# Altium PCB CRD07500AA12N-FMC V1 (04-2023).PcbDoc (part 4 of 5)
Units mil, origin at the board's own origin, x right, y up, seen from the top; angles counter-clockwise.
Board outline 8000 x 8000 mil, 4 copper layers (Top Layer, Layer 1, Layer 2, Bottom Layer), stack 107.988 mil thick; 393 components, 213 nets, 1142 pads, 380 vias.
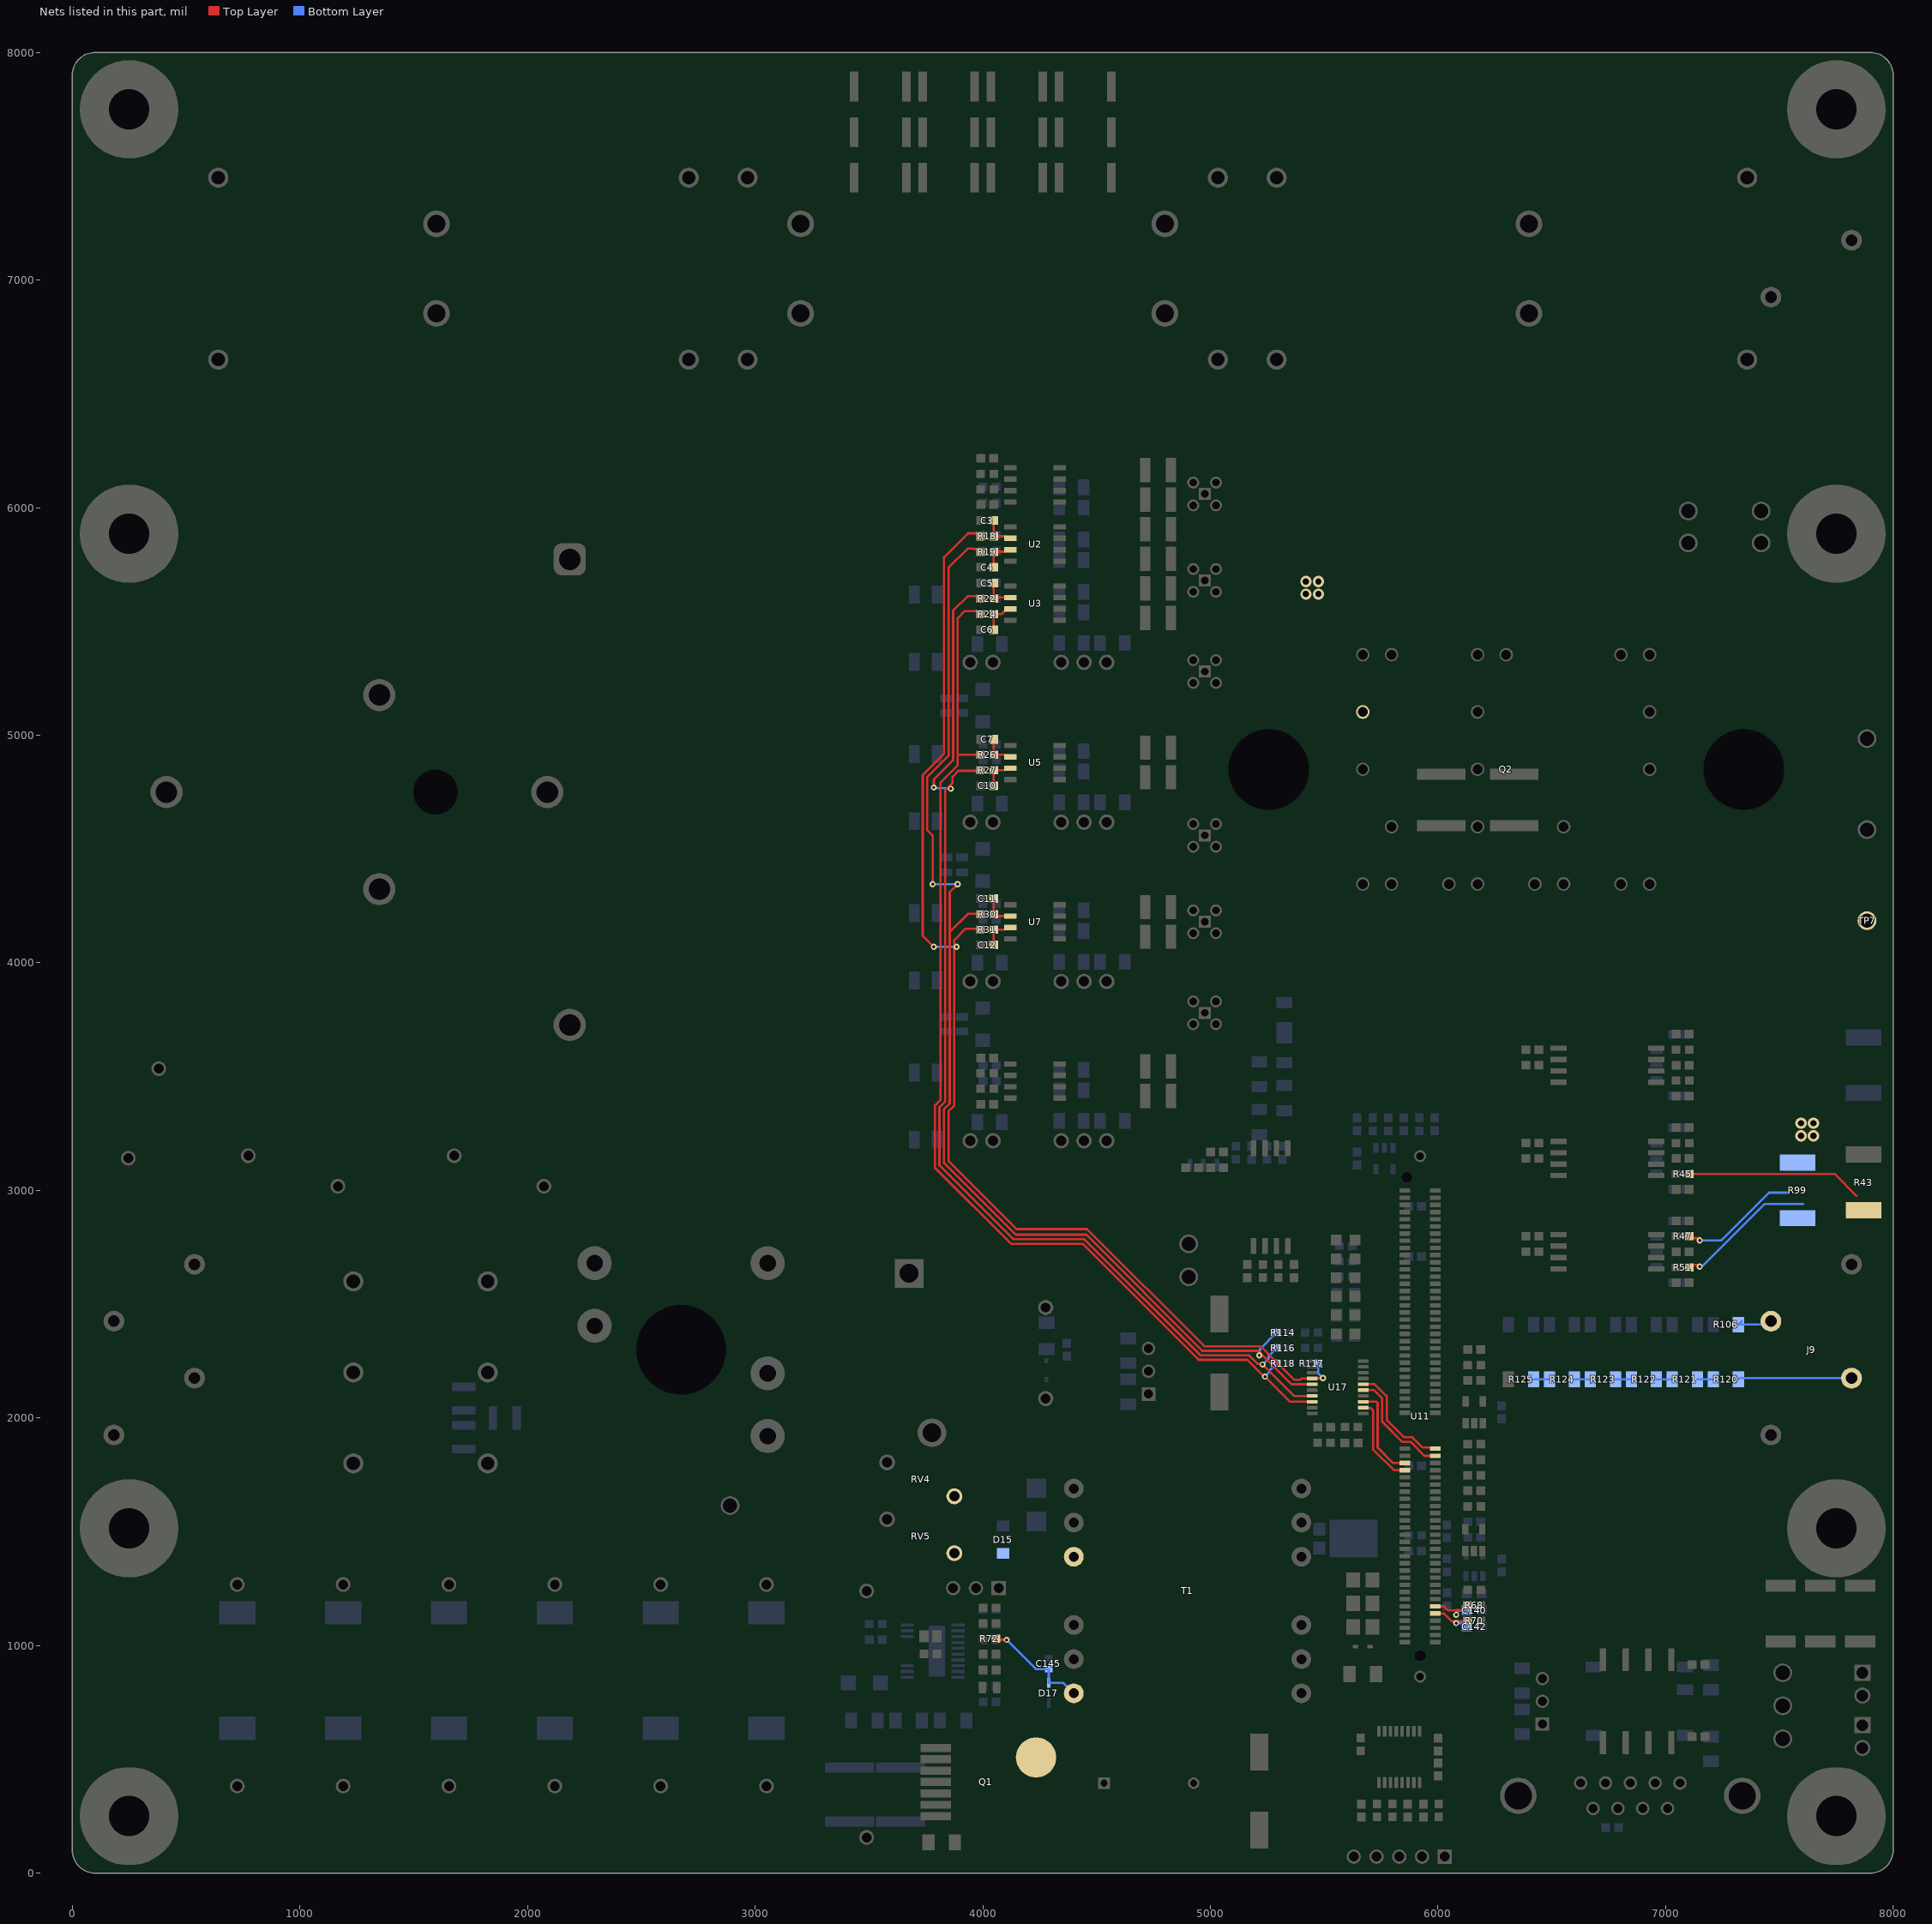
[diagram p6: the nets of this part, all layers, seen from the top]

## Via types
v1: diameter 27, hole 13, Top Layer to Bottom Layer, tented both sides, 367 vias
v2: diameter 50, hole 28, Top Layer to Bottom Layer, tented both sides, 13 vias

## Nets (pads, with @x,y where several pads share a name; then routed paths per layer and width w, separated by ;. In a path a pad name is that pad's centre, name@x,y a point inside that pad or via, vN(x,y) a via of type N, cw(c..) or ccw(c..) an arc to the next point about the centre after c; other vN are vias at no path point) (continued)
V_HS: R19.1 R30.1 R114.2 U17.15 | length 5303.9
  Top Layer w10: v1(3780,4345) 3780,4558.95 3756.5,4582.45 3756.5,4816.65 3850,4910.15 3850,5736.51 3933.19,5819.7 3956.81,5819.7 3957.55,5818.96 3978.42,5818.96 R19.1@3991.38,5806 ; v1(3890,4345) 3855,4310 3855,4135 ; R30.1@3991.38,4214 3990.38,4215 3935,4215 3855,4135 ; U17.15@5447.8,2147.8 5357.2,2147.8 5210,2295 4965.15,2295 4455.15,2805 4145,2805 3830,3120 3830,3356.35 3855,3381.35 3855,4135
  Bottom Layer w10: v1(3780,4345) v1(3890,4345) ; v1(5215,2275) 5218.25,2278.25 5218.25,2302.78 5290.47,2375 R114.2@5291.38,2375
V_HS+_FILT: C11.1 R30.2 U7.2 | length 141.7
  Top Layer w10: R30.2@4048.62,4214 4057.62,4205 U7.2@4121.73,4205 ; R30.2@4048.62,4217.2 4048.58,4217.25 C11.1@4048.58,4282
V_HS-_FILT: C4.1 R19.2 U2.3 | length 144.9
  Top Layer w10: C4.1@4048.58,5738 R19.2@4048.62,5806 R19.2@4048.62,5806 4096.98,5806 4105.98,5815 U2.3@4121.73,5815
V_HS_PWM: U11.53 U17.5 | length 476.7
  Top Layer w10: U17.5@5692.72,2122.87 5718.68,2122.87 5755,2086.56 5755,1982.99 5842.99,1895 5879.72,1895 5941.17,1833.54 U11.53@5988.86,1833.54
V_LS: R18.1 R31.1 R117.2 U17.14 | length 5321.1
  Top Layer w10: v1(3785,4070) 3736.5,4118.5 3736.5,4824.93 3830,4918.43 3830,5781.51 3935.6,5887.11 3956.48,5887.11 3956.64,5886.96 3978.42,5886.96 R18.1@3991.38,5874 ; R31.1@3991.38,4146 3987.38,4150 3925,4150 3875,4100 3875,4070 3875,3373.07 3850,3348.07 3850,3128.43 4148.43,2830 4458.43,2830 4973.43,2315 5220,2315 5367,2168 5395.39,2168 5400.78,2173.39 U17.14@5447.8,2173.39 5448.6,2174.19 5494.19,2174.19 v1(5495,2175)
  Bottom Layer w10: v1(3785,4070) v1(3885,4070) ; R117.2@5473.62,2240 5473.62,2196.38 v1(5495,2175)
V_LS+_FILT: C3.1 R18.2 U2.2 | length 145.9
  Top Layer w10: C3.1@4048.58,5943 R18.2@4048.62,5874 R18.2@4048.62,5874 4096.98,5874 4105.98,5865 U2.2@4121.73,5865
V_LS-_FILT: C12.1 R31.2 U7.3 | length 144.9
  Top Layer w10: C12.1@4048.58,4078 R31.2@4048.62,4146 R31.2@4048.62,4146 4096.98,4146 4105.98,4155 U7.3@4121.73,4155
V_LS_PWM: U11.55 U17.6 | length 474.2
  Top Layer w10: U17.6@5692.72,2148.46 5721.38,2148.46 5775,2094.84 5775,1991.27 5851.27,1915 5888,1915 5933.12,1869.88 5984.02,1869.88 U11.55@5988.86,1865.04
V_MEAS: C140.1 R68.2 U11.11 | length 237.4
  Top Layer w10: U11.11@5988.86,1172.13 6027.53,1172.13 6045.99,1153.67 6079.77,1153.67 6080,1153.43 ; v1(6080,1135) 6080,1153.43 ; R68.2@6131.38,1177 6130.47,1177 6108.61,1155.14 6081.7,1155.14 6080,1153.43
  Bottom Layer w10: v1(6080,1135) 6083.25,1138.25 6083.25,1143.65 6092.92,1153.32 6125.78,1153.32 C140.1@6127.45,1155
V_OUT: J9.3 R43.2 R45.1 R106.1 | length 946.6
  Top Layer w10: R45.1@7103.62,3072 7743.35,3072 7840,2975.35
  Bottom Layer w10: R106.1@7335.12,2425 R106.1@7320.12,2410 7447.83,2410 J9.3@7462.83,2425
VAR: RV4.2 RV5.1
W: Q2.W R47.1 R99.1 TP7.1 | length 533.2
  Top Layer w10: R47.1@7103.62,2808 7103.62,2803.86 7117.48,2790 v1@7150,2790
  Bottom Layer w10: v1(7150,2780) 7245,2780 7455,2990 7540,2990
  other v2: 7595,3240 7650,3240 7595,3295 7650,3295 5420,5620 5475,5620 5420,5675 5475,5675
W0: R120.2 R121.1 | length 69.6
  Bottom Layer w10: R121.1@7140.24,2170 R120.2@7209.88,2170
W1: R121.2 R122.1 | length 69.9
  Bottom Layer w10: R122.1@6960.12,2170 R121.2@7030,2170
W2: R122.2 R123.1 | length 69.8
  Bottom Layer w10: R123.1@6780.12,2170 R122.2@6849.88,2170
W3: R123.2 R124.1 | length 69.6
  Bottom Layer w10: R124.1@6600.24,2170 R123.2@6669.88,2170
W4: R124.2 R125.1 | length 69.8
  Bottom Layer w10: R125.1@6420.24,2170 R124.2@6490,2170
W_HS: R24.1 R26.1 R118.2 U17.18 | length 4842.2
  Top Layer w10: R26.1@3991.38,4914 3890,4914 ; R24.1@3991.38,5532 3978.42,5544.96 3957.55,5544.96 3956.81,5545.7 3920.7,5545.7 3890,5515 3890,4914 ; U17.18@5447.8,2071.02 5350.2,2071.02 v1(5240,2181.23) 5235.49,2181.23 5161.72,2255 4948.58,2255 4438.58,2765 4125,2765 3790,3100 3790,3372.92 3815,3397.92 3815,4793.28 3890,4868.28 3890,4914
  Bottom Layer w10: v1(5240,2181.23) 5240,2182.46 5259.54,2201.99 5259.54,2209.07 5290.47,2240 R118.2@5291.38,2240
W_HS+_FILT: C7.1 R26.2 U5.2 | length 144.9
  Top Layer w10: C7.1@4048.58,4982 R26.2@4048.62,4914 R26.2@4048.62,4914 4096.98,4914 4105.98,4905 U5.2@4121.73,4905
W_HS-_FILT: C6.1 R24.2 U3.3 | length 150.7
  Top Layer w10: C6.1@4048.58,5464 R24.2@4048.62,5532 R24.2@4048.62,5532 4082.98,5532 4105.98,5555 U3.3@4121.73,5555
W_HS_PWM: U11.50 U17.2 | length 392.3
  Top Layer w10: U17.2@5677.2,2045.43 5679.92,2042.72 5705.89,2042.72 5715,2033.6 5715,1861.72 5806.16,1770.55 U11.50@5855,1770.55
W_LS: R22.1 R27.1 R116.2 U17.17 | length 5083.2
  Top Layer w10: v1(3785,4770) 3785,4805 3870,4890 3870,5547.51 3933.19,5610.7 3980.67,5610.7 R22.1@3991.38,5600 ; v1(3860,4765) 3841.35,4765 ; R27.1@3991.38,4846 3988.88,4843.5 3893.5,4843.5 3867.43,4817.43 3867.43,4791.07 3841.35,4765 ; U17.17@5447.8,2096.61 5368.08,2096.61 5226.75,2237.95 5207.05,2237.95 5170,2275 4956.86,2275 4446.86,2785 4135,2785 3810,3110 3810,3364.64 3835,3389.64 3835,4758.65 3841.35,4765
  Bottom Layer w10: v1(3785,4770) 3787.5,4767.5 3857.5,4767.5 v1(3860,4765) ; v1(5230,2234.69) 5256.53,2261.23 5256.53,2273.06 5290.47,2307 R116.2@5291.38,2307
W_LS+_FILT: C5.1 R22.2 U3.2 | length 143.2
  Top Layer w10: C5.1@4048.58,5668 C5.1@4048.58,5668 R22.2@4048.62,5600 4053.62,5605 U3.2@4121.73,5605
W_LS-_FILT: C10.1 R27.2 U5.3 | length 144.9
  Top Layer w10: C10.1@4048.58,4778 R27.2@4048.62,4846 R27.2@4048.62,4846 4096.98,4846 4105.98,4855 U5.3@4121.73,4855
W_LS_PWM: U11.52 U17.3 | length 388.7
  Top Layer w10: U17.3@5692.72,2071.69 5729.14,2071.69 5735,2065.84 5735,1870 5802.95,1802.05 U11.52@5855,1802.05
W_MEAS: C142.1 R70.2 U11.9 | length 219.9
  Top Layer w10: U11.9@5988.86,1140.63 6027.48,1140.63 6061.61,1106.5 v1@6080,1106.5 ; v1(6080,1098) v1@6080,1106.5 ; R70.2@6131.38,1109 6128.88,1106.5 v1@6080,1106.5
  Bottom Layer w10: v1(6080,1098) 6080.08,1097.92 6109.64,1097.92 6124.57,1083 C142.1@6127.45,1083
W_OUT: J9.2 R51.1 R99.2 R120.1 | length 1117.5
  Top Layer w10: R51.1@7103.62,2672 7138.4,2672 7145.4,2665 v1(7150,2665)
  Bottom Layer w10: v1(7150,2665) 7153.25,2668.25 7163.25,2668.25 7435.35,2940.35 7605,2940.35 ; R120.1@7320.12,2170 7325.12,2175 J9.2@7817.17,2175
XFMR3: D15.2 Q1.8 T1.3 | length 26.1
  Top Layer w10: Q1.8@4235.66,507.76 Q1.8@4240,512.1 ; T1.3@4380,1390 T1.3@4400,1390
XFMR6: C145.1 D17.2 R72.2 T1.6 | length 476.6
  Top Layer w10: R72.2@4058.62,1030 4063.62,1025 v1(4105,1025)
  Bottom Layer w10: v1(4105,1025) 4233.62,896.38 C145.1@4290,896.38 D17.2@4290,835.28 4354.72,835.28 T1.6@4400,790
pads on no net: D1.6 HS1.3 HS1.4 J13.1 J13.4 J13.6 J13.8 L1.MH1 MH1.1 MH2.1 MH3.1 MH4.1 Q2.MH1 Q2.MH2 T1.2 T1.4 T1.7 T1.12 U11. U11.1 U11.2 U11.3 U11.4 U11.5 U11.6 U11.7 U11.8 U11.12 U11.14 U11.15 U11.18 U11.20 U11.21 U11.23 U11.24 U11.25 U11.26 U11.27 U11.28 U11.31 U11.32 U11.33 U11.34 U11.36 U11.37 U11.39 U11.40 U11.41 U11.42 U11.43 U11.44 U11.45 U11.54 U11.56 U11.57 U11.58 U11.59 U11.60 U11.61 U11.62 U11.63 U11.64 U11.66 U11.67 U11.69 U11.71 U11.72 U11.73 U11.75 U11.76 U11.77 U11.78 U11.79 U11.80 U11.81 U11.82 U11.85 U11.86 U11.89 U11.90 U11.91 U11.92 U11.94 U11.104 U11.106 U11.110 U11.113 U11.114 U11.115 U11.116 U11.117 U11.118 U11.119 U11.121 U11.122 U17.13 U17.16 U22.5 U22.6 U22.7 U22.10 U22.11 U22.12 U31.8

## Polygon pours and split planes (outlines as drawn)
V on Top Layer "V_L01_P141" (solid, pour order 141): 26 vertices, not listed, extent 6115,3070 7970,5155
G2 on Top Layer "G2_L01_P238" (solid, pour order 238): 6845,5450 6900,5395 6900,5387.5 6900,5325 6960,5325 6960,5495 5255,5495 5150,5600 5150,5805 5150,6220 4800,6220 4800,5980 5075,5980 5075,5570 5195,5450
G4 on Top Layer "G4_L01_P221" (solid, pour order 221): 6090,5395 6090,5390 6145,5335 6145,5325 6205,5325 6205,5440 5180,5440 5025,5595 5025,5960 4800,5960 4800,5720 4955,5720 4955,5585 5145,5395
G6 on Top Layer "G6_L01_P123" (solid, pour order 123): 4895,5460.84 4950,5405.84 4950,5395 4950,5255 5000,5255 5000,5420 5095,5325 5705,5325 5705,5385 5130,5385 4915,5600 4915,5700 4800,5700 4800,5460.84
C_FILT on Top Layer "C_FILT_L01_P047" (solid, pour order 47): 21 vertices, not listed, extent 930,2325 2385,5265
U on Top Layer "U_L01_P358" (solid, pour order 358): 7120,5020 7225,5125 7610,5125 7945,5125 7945,5315 7155,5315 7030,5190 6845,5190 6845,5020
G1 on Top Layer "G1_L01_P078" (solid, pour order 78): 18 vertices, not listed, extent 4800,3360 6960,4380
G3 on Top Layer "G3_L01_P054" (solid, pour order 54): 4920,4105 4950,4075 6260,4075 6390,4205 6390,4380 6594.94,4380 6594.95,4329.95 6290,4025 4800,4025 4800,4300 4920,4300 4920,4200 5025,4200 5025,4160 4920,4160
G5 on Top Layer "G5_L01_P053" (solid, pour order 53): 23 vertices, not listed, extent 4800,4170 6220,5000
G5H on Top Layer "G5H_L01_P192" (solid, pour order 192): 4310,4840 4310,4870 4740,4870 4740,4760 4425,4760 4425,4840
G5L on Top Layer "G5L_L01_P191" (solid, pour order 191): 4310,4920 4310,4890 4740,4890 4740,5000 4425,5000 4425,4920
G3H on Top Layer "G3H_L01_P188" (solid, pour order 188): 4310,4140 4310,4170 4740,4170 4740,4060 4425,4060 4425,4140
G3L on Top Layer "G3L_L01_P183" (solid, pour order 183): 4310,4220 4310,4190 4740,4190 4740,4300 4425,4300 4425,4220
G1H on Top Layer "G1H_L01_P180" (solid, pour order 180): 4310,3440 4310,3470 4720,3470 4720,3360 4425,3360 4425,3440
G1L on Top Layer "G1L_L01_P177" (solid, pour order 177): 4310,3520 4310,3490 4720,3490 4720,3600 4425,3600 4425,3520
G2L on Top Layer "G2L_L01_P203" (solid, pour order 203): 4310,6140 4310,6110 4740,6110 4740,6220 4425,6220 4425,6140
B_FILT on Top Layer "B_FILT_L01_P046" (solid, pour order 46): 1265,4425 1265,4215 1970,4215 2375,3810 2375,2960 2965,2370 2965,2120 3170,2120 3170,2300 2505,2965 2505,3940 2020,4425
A_FILT on Top Layer "A_FILT_L01_P045" (solid, pour order 45): 2805,3190 3245,2750 3245,2600 3030,2600 2655,2975 2655,4030 1995,4690 1995,4850 2155,4850 2805,4200
+3.3V on Top Layer "+3.3V_L01_P014" (solid, pour order 14): 33 vertices, not listed, extent 5625,460 7945,1070
SL on Top Layer "SL_L01_P246" (solid, pour order 246): 4925,3270 4925,3180 4925,3080 5020,3080 5020,3200 5090,3200 5090,3115 5370,3115 5370,3135 5265,3135 5265,3270
XFMR3 on Top Layer "XFMR3_L01_P295" (solid, pour order 295): 4170,645 4140,615 4115,615 4115,170 4405,170 4405,645 4340,645 4340,1280 4390,1330 4460,1330 4460,1445 4170,1445
GND on Top Layer "GND_L01_P314" (solid, pour order 314): 5165,105 5300,105 5300,335 5165,335
DC+ on Top Layer "DC+_L01_P348" (solid, pour order 348): 4585,7535 4635,7585 4925,7585 4925,7535 4975,7535 4975,7395 5080,7395 5080,7920 4545,7920 4545,7385 4585,7385
BLEED1 on Top Layer "BLEED1_L01_P346" (solid, pour order 346): 4245,7920 4355,7920 4355,7385 4245,7385
EGND1 on Top Layer "EGND1_L01_P342" (solid, pour order 342): 7435,1295 7435,1205 7925,1205 7925,1295
GND on Top Layer "GND_L01_P319" (solid, pour order 319): 5745,1360 5745,835 5670,835 5670,1360
+12V on Top Layer "+12V_L01_P318" (solid, pour order 318): 5560,1360 5560,835 5650,835 5650,1360
B on Top Layer "B_L01_P019" (solid, pour order 19): 100,2515 100,2355 875,2355 1110,2120 1315,2120 1315,2280 1170,2280 935,2515
C on Top Layer "C_L01_P394" (solid, pour order 394): 455,2255 455,2095 615,2095 990,1720 1315,1720 1315,1880 1060,1880 685,2255
DC+ on Top Layer "DC+_L01_P391" (solid, pour order 391): 5905,4568.03 5905,4635 6445,4635 6445,4568.03
DC- on Top Layer "DC-_L01_P390" (solid, pour order 390): 5905,4880 5905,4800 6445,4800 6445,4880
N_X_O on Top Layer "N_X_O_L01_P388" (solid, pour order 388): 2065,435 2065,330 3105,330 3105,435
-3V_LS on Top Layer "-3V_LS_L01_P197" (solid, pour order 197): 4310,5925 4380,5925 4380,5960 4405,5960 4405,5900 4310,5900
+3.3V on Top Layer "+3.3V_L01_P370" (solid, pour order 370): 6465,2670 6465,2605 6570,2605 6570,2670
GND on Top Layer "GND_L01_P369" (solid, pour order 369): 6475,2845 6475,2790 6570,2790 6570,2845
+3.3V on Top Layer "+3.3V_L01_P368" (solid, pour order 368): 6465,3080 6465,3015 6570,3015 6570,3080
GND on Top Layer "GND_L01_P367" (solid, pour order 367): 6475,3255 6475,3200 6570,3200 6570,3255
V_OUT on Top Layer "V_OUT_L01_P362" (solid, pour order 362): 7650,2375 7650,2710 7760,2820 7970,2820 7970,3000 7650,3000 7395,2745 7395,2375
S5 on Top Layer "S5_L01_P155" (solid, pour order 155): 6920,2790 6920,2885 7070,2885 7070,2845 7000,2845 7000,2790
+5V_V_HS on Top Layer "+5V_V_HS_L01_P142" (solid, pour order 142): 6920,3080 6920,2985 7070,2985 7070,3025 7000,3025 7000,3080
S3 on Top Layer "S3_L01_P151" (solid, pour order 151): 6920,3200 6920,3295 7070,3295 7070,3255 7000,3255 7000,3200
+5V_W_HS on Top Layer "+5V_W_HS_L01_P154" (solid, pour order 154): 6920,2670 6920,2575 7070,2575 7070,2615 7000,2615 7000,2670
S3 on Top Layer "S3_L01_P156" (solid, pour order 156): 7080,3025 7080,2985 7160,2985 7160,3050 7135,3050 7135,3025
S5 on Top Layer "S5_L01_P173" (solid, pour order 173): 7080,2615 7080,2575 7160,2575 7160,2640 7135,2640 7135,2615
-3V_U_HS on Top Layer "-3V_U_HS_L01_P174" (solid, pour order 174): 4310,3600 4310,3540 4370,3540 4370,3600
+15V_U_HS on Top Layer "+15V_U_HS_L01_P175" (solid, pour order 175): 4310,3360 4310,3420 4370,3420 4370,3360
-3V_V_HS on Top Layer "-3V_V_HS_L01_P181" (solid, pour order 181): 4310,4300 4310,4240 4370,4240 4370,4300
+15V_V_HS on Top Layer "+15V_V_HS_L01_P182" (solid, pour order 182): 4310,4060 4310,4120 4370,4120 4370,4060
-3V_W_HS on Top Layer "-3V_W_HS_L01_P189" (solid, pour order 189): 4310,5000 4310,4940 4370,4940 4370,5000
+15V_W_HS on Top Layer "+15V_W_HS_L01_P190" (solid, pour order 190): 4310,4760 4310,4820 4370,4820 4370,4760
-3V_LS on Top Layer "-3V_LS_L01_P193" (solid, pour order 193): 4310,5700 4310,5640 4370,5640 4370,5700
+15V_LS on Top Layer "+15V_LS_L01_P194" (solid, pour order 194): 4310,5460 4310,5520 4370,5520 4370,5460
G6L on Top Layer "G6L_L01_P195" (solid, pour order 195): 4310,5620 4310,5590 4740,5590 4740,5700 4425,5700 4425,5620
G6H on Top Layer "G6H_L01_P196" (solid, pour order 196): 4310,5540 4310,5570 4740,5570 4740,5460 4425,5460 4425,5540
+15V_LS on Top Layer "+15V_LS_L01_P198" (solid, pour order 198): 4310,5710 4310,5780 4370,5780 4370,5710
G4L on Top Layer "G4L_L01_P199" (solid, pour order 199): 4310,5880 4310,5850 4740,5850 4740,5960 4425,5960 4425,5880
G4H on Top Layer "G4H_L01_P200" (solid, pour order 200): 4310,5800 4310,5830 4740,5830 4740,5720 4425,5720 4425,5800
-3V_LS on Top Layer "-3V_LS_L01_P201" (solid, pour order 201): 4310,6190 4310,6160 4405,6160 4405,6190
+15V_LS on Top Layer "+15V_LS_L01_P202" (solid, pour order 202): 4310,5940 4310,6040 4365,6040 4365,5940
G2H on Top Layer "G2H_L01_P220" (solid, pour order 220): 4310,6060 4310,6090 4740,6090 4740,5980 4425,5980 4425,6060
+5V on Top Layer "+5V_L01_P247" (solid, pour order 247): 4090,3600 4090,3540 4155,3540 4155,3600
GND on Top Layer "GND_L01_P264" (solid, pour order 264): 4090,3360 4090,3420 4155,3420 4155,3360
+5V on Top Layer "+5V_L01_P265" (solid, pour order 265): 4090,4300 4090,4240 4155,4240 4155,4300
GND on Top Layer "GND_L01_P266" (solid, pour order 266): 4090,4060 4090,4120 4155,4120 4155,4060
+5V on Top Layer "+5V_L01_P267" (solid, pour order 267): 4090,5000 4090,4940 4155,4940 4155,5000
GND on Top Layer "GND_L01_P268" (solid, pour order 268): 4090,4760 4090,4820 4155,4820 4155,4760
+5V on Top Layer "+5V_L01_P269" (solid, pour order 269): 4090,5700 4090,5640 4155,5640 4155,5700
GND on Top Layer "GND_L01_P270" (solid, pour order 270): 4090,5460 4090,5520 4155,5520 4155,5460
+5V on Top Layer "+5V_L01_P271" (solid, pour order 271): 4090,5960 4090,5900 4155,5900 4155,5960
GND on Top Layer "GND_L01_P272" (solid, pour order 272): 4090,5720 4090,5780 4155,5780 4155,5720
+5V on Top Layer "+5V_L01_P273" (solid, pour order 273): 4090,6220 4090,6160 4155,6160 4155,6220
GND on Top Layer "GND_L01_P281" (solid, pour order 281): 4090,5980 4090,6040 4155,6040 4155,5980
DC- on Top Layer "DC-_L01_P349" (solid, pour order 349): 3080,7585 3025,7530 3025,7395 2920,7395 2920,7920 3455,7920 3455,7385 3415,7385 3415,7533.6 3363.6,7585
BLEED2 on Top Layer "BLEED2_L01_P345" (solid, pour order 345): 3645,7920 3755,7920 3755,7385 3645,7385
GND_ISO on Top Layer "GND_ISO_L01_P344" (solid, pour order 344): 7150,630 7150,570 7130,570 7130,540 7195,540 7195,630
GND on Top Layer "GND_L01_P332" (solid, pour order 332): 7390,1070 7390,975 7945,975 7945,1070
GND on Top Layer "GND_L01_P327" (solid, pour order 327): 6705,990 6705,885 6780,885 6780,990
GND on Top Layer "GND_L01_P323" (solid, pour order 323): 7145,995 7145,880 7215,880 7215,995
+5V_LS on Top Layer "+5V_LS_L01_P240" (solid, pour order 240): 5080,3080 5080,3190 5035,3190 5035,3080
+12V on Top Layer "+12V_L01_P322" (solid, pour order 322): 5000,2195 5000,2030 5125,2030 5125,2195
GND on Top Layer "GND_L01_P317" (solid, pour order 317): 5000,2535 5000,2375 5125,2375 5125,2535
GND_ISO on Top Layer "GND_ISO_L01_P316" (solid, pour order 316): 6710,630 6710,520 6780,520 6780,630
+5V_ISO on Top Layer "+5V_ISO_L01_P315" (solid, pour order 315): 7140,630 7140,575 7105,575 7105,515 7000,515 7000,630
+12V on Top Layer "+12V_L01_P313" (solid, pour order 313): 5165,615 5295,615 5295,410 5165,410
GND on Top Layer "GND_L01_P305" (solid, pour order 305): 6475,3665 6475,3610 6570,3610 6570,3665
+3.3V on Top Layer "+3.3V_L01_P312" (solid, pour order 312): 6465,3490 6465,3425 6570,3425 6570,3490
N_X_I on Top Layer "N_X_I_L01_P304" (solid, pour order 304): 1450,485 1500,435 1710,435 1710,330 670,330 670,435 1340,435 1390,485 1390,1490 1470,1570 1470,1995 1520,1995 1520,1540 1450,1470
FLY_S on Top Layer "FLY_S_L01_P289" (solid, pour order 289): 3705,80 3800,80 3800,225 3865,225 3865,470 3705,470
DC- on Top Layer "DC-_L01_P282" (solid, pour order 282): 3850,195 3850,75 4000,75 4000,195
+15V_LS on Top Layer "+15V_LS_L01_P239" (solid, pour order 239): 4870,3080 4915,3080 4915,3170 4870,3170
S1 on Top Layer "S1_L01_P157" (solid, pour order 157): 7080,3435 7080,3395 7160,3395 7160,3460 7135,3460 7135,3435
S1 on Top Layer "S1_L01_P153" (solid, pour order 153): 6920,3610 6920,3705 7070,3705 7070,3665 7000,3665 7000,3610
+5V_U_HS on Top Layer "+5V_U_HS_L01_P152" (solid, pour order 152): 6920,3490 6920,3395 7070,3395 7070,3435 7000,3435 7000,3490
MID on Top Layer "MID_L01_P052" (solid, pour order 52): 29 vertices, not listed, extent 1475,7010 6550,7920
A_FUSE on Top Layer "A_FUSE_L01_P049" (solid, pour order 49): 1485,3005 1892.5,2597.5 1790,2495 1375,2910 1375,3140 1065,3450 320,3450 320,3610 1110,3610 1485,3235
Bridge- on Top Layer "BRIDGE-_L01_P035" (solid, pour order 35): 2945,1680 2995,1680 2995,1730 3665,1730 3665,1803.82 3666.18,1805 3715,1805 3715,1850 3845,1850 3845,2020 2840,2020 2840,1575 2945,1575
A on Top Layer "A_L01_P015" (solid, pour order 15): 1065,2775 1160,2680 1315,2680 1315,2520 1120,2520 1025,2615 455,2615 455,2775
DC- on Bottom Layer "DC-_L04_P359" (solid, pour order 359): 59 vertices, not listed, extent 535,1205 7875,7920
+12V on Bottom Layer "+12V_L04_P406" (solid, pour order 406): 83 vertices, not listed, extent 3630,50 7945,5660
NetD12_1 on Bottom Layer "NETD12_1_L04_P136" (solid, pour order 136): 4245,2330 4245,2235 4315,2235 4315,2330
S5 on Bottom Layer "S5_L04_P326" (solid, pour order 326): 6220,4275 6225,4275 6280,4220 7080,4220 7280,4020 7212.5,3952.5 6995,4170 6010,4170 6010,4380 6220,4380
S3 on Bottom Layer "S3_L04_P381" (solid, pour order 381): 6905,3995 6875,4025 6270,4025 6270,4075 6955,4075 6970,4060 6970,3980 6905,3980
B_FILT on Bottom Layer "B_FILT_L04_P032" (solid, pour order 32): 2500,1770 2500,1065 2670,1065 2670,1775 2995,2100 3145,2100 3145,2290 3020,2290
SL on Bottom Layer "SL_BOT" (solid, pour order 209): 27 vertices, not listed, extent 4415,3080 5080,6190
NetC85_2 on Bottom Layer "NETC85_2_L04_P254" (solid, pour order 254): 3775,4675 3775,4540 4155,4540 4155,4740 4009.83,4740 4009.83,4570 3895,4570 3895,4675
B_FUSE on Bottom Layer "B_FUSE_L04_P404" (solid, pour order 404): 19 vertices, not listed, extent 1105,2120 2285,3825
GND_ISO on Bottom Layer "GND_ISO_L04_P403" (solid, pour order 403): 6595,440 6645,490 6645,630 7235,630 7235,490 7285,440 7395,440 7395,250 6295,250 6295,440
+5V_ISO on Bottom Layer "+5V_ISO_L04_P308" (solid, pour order 308): 6645,630 6645,505 6720,505 6720,630
no net on Bottom Layer "NONET_L04_P402" (solid, pour order 402): 7415,1995 7415,1880 7415,1200 7945,1200 7945,1995
C_FUSE on Bottom Layer "C_FUSE_L04_P389" (solid, pour order 389): 30 vertices, not listed, extent 170,1065 1875,4890
+5V on Bottom Layer "+5V_L04_P262" (solid, pour order 262): 4035,6220 4035,5577.2 4155,5577.2 4155,6220
GND on Bottom Layer "GND_L04_P261" (solid, pour order 261): 3775,6055 3940,6220 4025,6220 4025,5502.2 3775,5502.2
+5V on Bottom Layer "+5V_L04_P301" (solid, pour order 301): 7050,780 7220,780 7235,780 7235,870 7050,870
DC+ on Bottom Layer "DC+_L04_P287" (solid, pour order 287): 3305,250 3305,125 3750,125 3750,250
EGND0 on Bottom Layer "EGND0_L04_P320" (solid, pour order 320): 390,765 440,765 440,720 3140,720 3140,550 25,550 25,1975 465,1975 465,1415 390,1340
C_FILT on Bottom Layer "C_FILT_L04_P030" (solid, pour order 30): 2205,1220 2385,1400 2385,2475 2205,2475 2205,1425 2035,1255 2035,1065 2205,1065
A_FUSE on Bottom Layer "A_FUSE_L04_P028" (solid, pour order 28): 29 vertices, not listed, extent 1570,1065 2585,5960
B_FUSE on Bottom Layer "B_FUSE_L04_P023" (solid, pour order 23): 1105,1332.5 1105,1065 1275,1065 1275,1332.5
S5 on Bottom Layer "S5_L04_P168" (solid, pour order 168): 7065.2,2885 7065,2884.8 7065,2805 7010,2805 7010,2765 6920,2765 6920,2695 7010,2695 7010,2655 7065,2655 7065,2575 7160,2575 7160,2885
S1 on Bottom Layer "S1_L04_P165" (solid, pour order 165): 7065.2,3705 7065,3704.8 7065,3625 7010,3625 7010,3585 6920,3585 6920,3515 7010,3515 7010,3475 7065,3475 7065,3395 7160,3395 7160,3705
S3 on Bottom Layer "S3_L04_P148" (solid, pour order 148): 7065.2,3295 7065,3294.8 7065,3215 7010,3215 7010,3175 6920,3175 6920,3105 7010,3105 7010,3065 7065,3065 7065,2985 7160,2985 7160,3295
DC+ on Bottom Layer "DC+_L04_P386" (solid, pour order 386): 4190,1735 4190,1645 4450,1645 4450,1735
A_FILT on Bottom Layer "A_FILT_L04_P385" (solid, pour order 385): 2965,1330 2965,1065 3135,1065 3135,1330
VAR on Bottom Layer "VAR_L04_P383" (solid, pour order 383): 3825,1700 3825,1360 3925,1360 3925,1700
+3.3V on Bottom Layer "+3.3V_L04_P382" (solid, pour order 382): 5970,3225 5970,2975 6015,2975 6015,2540 6215,2540 6215,3225
-3V_LS on Bottom Layer "-3V_LS_L04_P208" (solid, pour order 208): 18 vertices, not listed, extent 4310,5285 4405,6190
+15V_LS on Bottom Layer "+15V_LS_L04_P216" (solid, pour order 216): 4310,6040 4310,5935 4365,5935 4365,6040
NetD9_2 on Bottom Layer "NETD9_2_L04_P380" (solid, pour order 380): 4035,5230 3810,5230 3810,5135 4035,5135
GND on Bottom Layer "GND_L04_P379" (solid, pour order 379): 3965,5020 3965,5090 4025,5090 4025,5020 4025,4800 3775,4800 3775,5020
NetD10_2 on Bottom Layer "NETD10_2_L04_P378" (solid, pour order 378): 4035,4530 3810,4530 3810,4435 4035,4435
GND on Bottom Layer "GND_L04_P377" (solid, pour order 377): 3965,4320 3965,4390 4025,4390 4025,4320 4025,4100 3775,4100 3775,4320
NetC78_2 on Bottom Layer "NETC78_2_L04_P376" (solid, pour order 376): 3775,5377.2 3775,5242.2 4155,5242.2 4155,5442.2 4009.83,5442.2 4009.83,5272.2 3895,5272.2 3895,5377.2
NetC78_1 on Bottom Layer "NETC78_1_L04_P375" (solid, pour order 375): 3765,5282.2 3765,5387.2 3905,5387.2 3905,5282.2 3975,5282.2 4000,5282.2 4000,5442.2 3675,5442.2 3675,5282.2
NetC106_2 on Bottom Layer "NETC106_2_L04_P374" (solid, pour order 374): 3775,3275 3775,3140 4155,3140 4155,3340 4009.83,3340 4009.83,3170 3895,3170 3895,3275
NetC106_1 on Bottom Layer "NETC106_1_L04_P373" (solid, pour order 373): 3765,3180 3765,3285 3905,3285 3905,3180 3975,3180 4000,3180 4000,3340 3675,3340 3675,3180
NetC92_2 on Bottom Layer "NETC92_2_L04_P372" (solid, pour order 372): 3775,3975 3775,3840 4155,3840 4155,4040 4009.83,4040 4009.83,3870 3895,3870 3895,3975
NetC92_1 on Bottom Layer "NETC92_1_L04_P371" (solid, pour order 371): 3765,3880 3765,3985 3905,3985 3905,3880 3975,3880 4000,3880 4000,4040 3675,4040 3675,3880
GND on Bottom Layer "GND_L04_P365" (solid, pour order 365): 6420,2775 6500,2775 6500,2845 6420,2845
+3.3V on Bottom Layer "+3.3V_L04_P364" (solid, pour order 364): 6420,2750 6420,2605 6500,2605 6500,2615 6500,2750
GND on Bottom Layer "GND_L04_P363" (solid, pour order 363): 6420,3185 6500,3185 6500,3255 6420,3255
+3.3V on Bottom Layer "+3.3V_L04_P360" (solid, pour order 360): 6420,3160 6420,3015 6500,3015 6500,3025 6500,3160
W_OUT on Bottom Layer "W_OUT_L04_P109" (solid, pour order 109): 7675,2965 7675,2800 7675,2600 7900,2375 7900,2115 7735,2115 7735,2355 7475,2615 7475,2965
W on Bottom Layer "W_L04_P127" (solid, pour order 127): 7670,3320 7675,3315 7675,2975 7475,2975 7475,3250 7545,3320
U_OUT on Bottom Layer "U_OUT_L04_P126" (solid, pour order 126): 7770,2644.54 7800,2615 7970,2615 7970,3515 7770,3515 7770,2760
U on Bottom Layer "U_L04_P048" (solid, pour order 48): 7575,3910 7770,3715 7770,3585 7970,3585 7970,3905 7745,4130 7745,4642.37 7945,4837.38 7945,5315 7575,5315
W on Bottom Layer "W_L04_P356" (solid, pour order 356): 5620,5225 5545,5300 5545,5315 5545,5705 5380,5705 5380,5285 5635,5030 5730,5030 5730,5200 5730,5225
GND on Bottom Layer "GND_L04_P355" (solid, pour order 355): 6420,3595 6500,3595 6500,3665 6420,3665
+3.3V on Bottom Layer "+3.3V_L04_P354" (solid, pour order 354): 6420,3570 6420,3425 6500,3425 6500,3435 6500,3570
+5V_V_HS on Bottom Layer "+5V_V_HS_L04_P137" (solid, pour order 137): 7055,3055 7055,2985 6920,2985 6920,3095 7000,3095 7000,3055
+15V_V_HS on Bottom Layer "+15V_V_HS_L04_P147" (solid, pour order 147): 7055,3225 7055,3295 6920,3295 6920,3185 7000,3185 7000,3225
+5V_W_HS on Bottom Layer "+5V_W_HS_L04_P166" (solid, pour order 166): 7055,2645 7055,2575 6920,2575 6920,2685 7000,2685 7000,2645
+15V_W_HS on Bottom Layer "+15V_W_HS_L04_P167" (solid, pour order 167): 7055,2815 7055,2885 6920,2885 6920,2775 7000,2775 7000,2815
+15V_LS on Bottom Layer "+15V_LS_L04_P207" (solid, pour order 207): 4595,5355 4500,5355 4500,5285 4595,5285 4745,5285 4745,4875 4745,3080 4870,3080 4875,3080 4925,3080 4925,3268.95 4765,3420.77 4765,5442.2 4595,5442.2
S1 on Bottom Layer "S1_L04_P353" (solid, pour order 353): 4565,3265 4487.5,3265 4487.5,3180 4395,3180 4395,3255 4415,3255 4415,3600 4650,3600 4650,3355 4565,3355
-3V_U_HS on Bottom Layer "-3V_U_HS_L04_P352" (solid, pour order 352): 4405,3264.75 4404.75,3265 4385,3265 4385,3180 4310,3180 4310,3340 4380,3340 4380,3495 4310,3495 4310,3600 4405,3600
+15V_U_HS on Bottom Layer "+15V_U_HS_L04_P351" (solid, pour order 351): 4500,3180 4500,3255 4580,3255 4580,3340 4650,3340 4650,3180
S5 on Bottom Layer "S5_L04_P350" (solid, pour order 350): 4565,4665 4487.5,4665 4487.5,4580 4395,4580 4395,4655 4415,4655 4415,5000 4650,5000 4650,4755 4565,4755
-3V_W_HS on Bottom Layer "-3V_W_HS_L04_P343" (solid, pour order 343): 4405,4664.75 4404.75,4665 4385,4665 4385,4580 4310,4580 4310,4740 4380,4740 4380,4895 4310,4895 4310,5000 4405,5000
+15V_W_HS on Bottom Layer "+15V_W_HS_L04_P341" (solid, pour order 341): 4500,4580 4500,4655 4580,4655 4580,4740 4650,4740 4650,4580
+15V_U_HS on Bottom Layer "+15V_U_HS_L04_P169" (solid, pour order 169): 4310,3475 4310,3360 4370,3360 4370,3475
+15V_V_HS on Bottom Layer "+15V_V_HS_L04_P178" (solid, pour order 178): 4310,4175 4310,4060 4370,4060 4370,4175
+15V_W_HS on Bottom Layer "+15V_W_HS_L04_P187" (solid, pour order 187): 4310,4875 4310,4760 4370,4760 4370,4875
+15V_LS on Bottom Layer "+15V_LS_L04_P210" (solid, pour order 210): 4310,5577.2 4310,5462.2 4370,5462.2 4370,5577.2
+15V_LS on Bottom Layer "+15V_LS_L04_P211" (solid, pour order 211): 4310,5805 4310,5710 4370,5710 4370,5805
+15V_V_HS on Bottom Layer "+15V_V_HS_L04_P217" (solid, pour order 217): 4500,3880 4500,3955 4580,3955 4580,4040 4650,4040 4650,3880
-3V_V_HS on Bottom Layer "-3V_V_HS_L04_P225" (solid, pour order 225): 4405,3964.75 4404.75,3965 4385,3965 4385,3880 4310,3880 4310,4040 4380,4040 4380,4195 4310,4195 4310,4300 4405,4300
S3 on Bottom Layer "S3_L04_P226" (solid, pour order 226): 4565,3965 4487.5,3965 4487.5,3880 4395,3880 4395,3955 4415,3955 4415,4300 4650,4300 4650,4055 4565,4055
GND on Bottom Layer "GND_L04_P236" (solid, pour order 236): 3965,3620 3965,3690 4025,3690 4025,3620 4025,3400 3775,3400 3775,3620
+5V on Bottom Layer "+5V_L04_P248" (solid, pour order 248): 4035,3620 4035,3460 4155,3460 4155,3620
NetC85_1 on Bottom Layer "NETC85_1_L04_P253" (solid, pour order 253): 3765,4580 3765,4685 3905,4685 3905,4580 3975,4580 4000,4580 4000,4740 3675,4740 3675,4580
+5V on Bottom Layer "+5V_L04_P258" (solid, pour order 258): 4035,4320 4035,4175 4155,4175 4155,4320
+5V on Bottom Layer "+5V_L04_P260" (solid, pour order 260): 4035,5020 4035,4875 4155,4875 4155,5020
NetD11_2 on Bottom Layer "NETD11_2_L04_P336" (solid, pour order 336): 4035,3830 3810,3830 3810,3735 4035,3735
+3.3V on Bottom Layer "+3.3V_L04_P340" (solid, pour order 340): 6330,830 6425,830 6425,820 6495,820 6495,930 6330,930
DC- on Bottom Layer "DC-_L04_P293" (solid, pour order 293): 3600,440 3600,410 3750,410 3750,490 3305,490 3305,440
+5V_LS on Bottom Layer "+5V_LS_L04_P227" (solid, pour order 227): 5015,3140 5015,3080 5075,3080 5075,3160 5050,3160 5050,3140
+5V on Bottom Layer "+5V_L04_P310" (solid, pour order 310): 4605,2375 4605,2280 4770,2280 4770,2375
GND on Bottom Layer "GND_L04_P309" (solid, pour order 309): 6330,820 6330,690 6410,690 6410,720 6495,720 6495,790 6410,790 6410,820
+5V_ISO on Bottom Layer "+5V_ISO_L04_P307" (solid, pour order 307): 7115,520 7115,450 7235,450 7235,520
GND_ISO on Bottom Layer "GND_ISO_L04_P306" (solid, pour order 306): 7050,580 7115,580 7115,540 7235,540 7235,630 7050,630
GND on Bottom Layer "GND_L04_P300" (solid, pour order 300): 7135,995 7135,940 7050,940 7050,880 7235,880 7235,995
GND on Bottom Layer "GND_L04_P294" (solid, pour order 294): 4605,2270 4605,2140 4770,2140 4770,2270
XFMR3 on Bottom Layer "XFMR3_L04_P292" (solid, pour order 292): 4055,1430 4055,1375 4335,1375 4335,1330 4460,1330 4460,1430
DC+_D on Bottom Layer "DC+_D_L04_P290" (solid, pour order 290): 4060,1590 4060,1500 4280,1500 4280,1590
DC- on Bottom Layer "DC-_L04_P284" (solid, pour order 284): 3850,1005 3960,1005 3960,975 3850,975 3850,870 3920,870 3920,815 3850,815 3760,815 3760,1150 3850,1150
FLY+1 on Bottom Layer "FLY+1_L04_P286" (solid, pour order 286): 3705,710 3705,630 3840,630 3840,710
FLY+0 on Bottom Layer "FLY+0_L04_P285" (solid, pour order 285): 3510,710 3510,630 3645,630 3645,710
DC+ on Bottom Layer "DC+_L04_P283" (solid, pour order 283): 3445,875 3445,630 3330,630 3330,875
FLY_IN on Bottom Layer "FLY_IN_L04_P278" (solid, pour order 278): 3640,925 3640,870 3515,870 3515,800 3700,800 3700,925
NetD14_1,2 on Bottom Layer "NETD14_1,2_L04_P263" (solid, pour order 263): 5340,1600 5340,1340 5505,1340 5505,1600
+15V_U_HS on Bottom Layer "+15V_U_HS_L04_P164" (solid, pour order 164): 7055,3635 7055,3705 6920,3705 6920,3595 7000,3595 7000,3635
+5V_U_HS on Bottom Layer "+5V_U_HS_L04_P150" (solid, pour order 150): 7055,3465 7055,3395 6920,3395 6920,3505 7000,3505 7000,3465
GND on Bottom Layer "GND_L04_P128" (solid, pour order 128): 4315,2445 4400,2445 4400,2310 4340,2310 4340,2340 4245,2340 4245,2520 4315,2520
B_FUSE on Bottom Layer "B_FUSE_L04_P029" (solid, pour order 29): 19 vertices, not listed, extent 1105,2120 2285,3825
N_X_I on Bottom Layer "N_X_I_L04_P020" (solid, pour order 20): 1665,2000 1665,1995 1470,1995 1470,1945 1565,1945 1665,1945 1875,1945 1875,2055 1665,2055
DC+ on Layer 2 "DC+_L03_P027" (solid, pour order 27): 68 vertices, not listed, extent 600,95 7525,7920
+15V_W_HS on Layer 2 "+15V_W_HS_L03_P112" (solid, pour order 112): 22 vertices, not listed, extent 4310,2830 7445,5000
+5V on Layer 2 "+5V_L03_P139" (solid, pour order 139): 56 vertices, not listed, extent 3630,50 7945,6240
+3.3V on Layer 2 "+3.3V_L03_P329" (solid, pour order 329): 27 vertices, not listed, extent 5070,965 6570,3665
B_FUSE on Layer 2 "B_FUSE_L03_P407" (solid, pour order 407): 19 vertices, not listed, extent 1105,2120 2285,3825
+15V_LS on Layer 2 "+15V_LS_L03_P276" (solid, pour order 276): 4310,5285 4720,5285 4720,6220 4310,6220
A_FUSE on Layer 2 "A_FUSE_L03_P405" (solid, pour order 405): 27 vertices, not listed, extent 1570,1065 2585,5960
C_FUSE on Layer 2 "C_FUSE_L03_P036" (solid, pour order 36): 29 vertices, not listed, extent 170,1065 1875,4890
+5V_LS on Layer 2 "+5V_LS_L03_P235" (solid, pour order 235): 4870,3185 4925,3185 4925,3270 5370,3270 5370,3115 5080,3115 5080,3080 4870,3080
EGND1 on Layer 2 "EGND1_L03_P330" (solid, pour order 330): 7415,1995 7415,1880 7415,1200 7945,1200 7945,1995
+5V_U_HS on Layer 2 "+5V_U_HS_L03_P241" (solid, pour order 241): 7045,3705 7045,3640 6920,3640 6920,3395 7160,3395 7160,3705
+15V_U_HS on Layer 2 "+15V_U_HS_L03_P110" (solid, pour order 110): 20 vertices, not listed, extent 4310,3180 7035,3915
+15V_V_HS on Layer 2 "+15V_V_HS_L03_P111" (solid, pour order 111): 17 vertices, not listed, extent 4310,3240 7305,4300
+5V_W_HS on Layer 2 "+5V_W_HS_L03_P242" (solid, pour order 242): 6920,2575 7160,2575 7160,2830 6920,2830
+5V_V_HS on Layer 2 "+5V_V_HS_L03_P243" (solid, pour order 243): 6920,2985 7160,2985 7160,3230 6920,3230
+3.3V on Layer 2 "+3.3V_L03_P331" (solid, pour order 331): 5640,635 5640,530 6020,530 6020,635
+5V_ISO on Layer 2 "+5V_ISO_L03_P328" (solid, pour order 328): 6645,630 7235,630 7235,440 7235,250 6445,250 6445,440 6645,440
W on Layer 1 "W_L02_P335" (solid, pour order 335): 7745,4220 7900,4220 7900,4150 7745,4150 7745,3160 7740,3155 7575,3155 7575,5185 7165,5595 5390,5595 5390,5705 7245,5705 7745,5205
SL on Layer 1 "SL_L02_P245" (solid, pour order 245): 5150,5600 5255,5495 6970,5495 6970,5325 4720,5325 4720,5285 4310,5285 4310,5325 4310,6220 5150,6220
GND on Layer 1 "GND_L02_P061" (solid, pour order 61): 56 vertices, not listed, extent 3630,50 7945,6240
S5 on Layer 1 "S5_L02_P334" (solid, pour order 334): 6920,2885 6920,2575 7160,2575 7160,2650 7165,2650 7205,2650 7445,2890 7445,3850 7200,4095 7135,4030 7405,3760 7405,2965 7325,2885
S3 on Layer 1 "S3_L02_P298" (solid, pour order 298): 6920,3295 6920,2985 7160,2985 7160,3100 7305,3100 7305,3725 6955,4075 6905,4075 6905,3980 7000,3980 7260,3720 7260,3295
S1 on Layer 1 "S1_L02_P179" (solid, pour order 179): 31 vertices, not listed, extent 4310,3180 7160,4380
C_FILT on Layer 1 "C_FILT_L02_P393" (solid, pour order 393): 21 vertices, not listed, extent 930,2325 2385,5265
S5 on Layer 1 "S5_L02_P244" (solid, pour order 244): 17 vertices, not listed, extent 4310,4170 6220,5000
S3 on Layer 1 "S3_L02_P121" (solid, pour order 121): 20 vertices, not listed, extent 4310,3880 6595,4380
A_FILT on Layer 1 "A_FILT_L02_P033" (solid, pour order 33): 21 vertices, not listed, extent 1995,1210 3390,4850
B_FILT on Layer 1 "B_FILT_L02_P395" (solid, pour order 395): 1265,4425 1265,4215 1970,4215 2375,3810 2375,2960 2965,2370 2965,2120 3170,2120 3170,2300 2505,2965 2505,3940 2020,4425
A_FUSE on Layer 1 "A_FUSE_L02_P400" (solid, pour order 400): 1485,3005 1892.5,2597.5 1790,2495 1375,2910 1375,3140 1065,3450 320,3450 320,3610 1110,3610 1485,3235
SL on Layer 1 "SL_L02_P234" (solid, pour order 234): 4870,3185 4925,3185 4925,3270 5370,3270 5370,3115 5080,3115 5080,3080 4870,3080
B_FUSE on Layer 1 "B_FUSE_L02_P399" (solid, pour order 399): 18 vertices, not listed, extent 1105,1195 2110,2250
N_X_I on Layer 1 "N_X_I_L02_P398" (solid, pour order 398): 670,435 670,330 1710,330 1710,435
EGND1 on Layer 1 "EGND1_L02_P396" (solid, pour order 396): 7415,1995 7415,1880 7415,1200 7945,1200 7945,1995
A on Layer 1 "A_L02_P387" (solid, pour order 387): 1065,2775 1160,2680 1315,2680 1315,2520 1120,2520 1025,2615 455,2615 455,2775
C on Layer 1 "C_L02_P361" (solid, pour order 361): 455,2255 455,2095 615,2095 990,1720 1315,1720 1315,1880 1060,1880 685,2255
B on Layer 1 "B_L02_P392" (solid, pour order 392): 100,2515 100,2355 875,2355 1110,2120 1315,2120 1315,2280 1170,2280 935,2515
GND_ISO on Layer 1 "GND_ISO_L02_P288" (solid, pour order 288): 6595,440 6645,490 6645,630 7235,630 7235,490 7285,440 7395,440 7395,250 6295,250 6295,440
DC- on Layer 1 "DC-_L02_P397" (solid, pour order 397): 25 vertices, not listed, extent 3435,50 4565,2740

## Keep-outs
Top Layer:
  lines w10: 95,2400 ccw(c145,2400) 145,2350 ; 95,2470 cw(c145,2470) 145,2520 ; 315,3495 ccw(c365,3495) 365,3445 ; 315,3565 cw(c365,3565) 365,3615 ; 450,2140 ccw(c500,2140) 500,2090 ; 450,2210 cw(c500,2210) 500,2260 ; 450,2660 ccw(c500,2660) 500,2610 ; 450,2730 cw(c500,2730) 500,2780 ; 665,374.17 ccw(c715,374.17) 715,324.17 ; 665,389.17 cw(c715,389.17) 715,439.17 ; 1260,4260 ccw(c1310,4260) 1310,4210 ; 1260,4380 cw(c1310,4380) 1310,4430 ; 1270,1715 ccw(c1270,1765) 1320,1765 ; 1270,1885 cw(c1270,1835) 1320,1835 ; 1270,2115 ccw(c1270,2165) 1320,2165 ; 1270,2285 cw(c1270,2235) 1320,2235 ; 1270,2515 ccw(c1270,2565) 1320,2565 ; 1270,2685 cw(c1270,2635) 1320,2635 ; 1335,440 ccw(c1335,490) 1385,490 ; 1385,5270 cw(c1385,5220) 1435,5220 ; 1455,490 ccw(c1505,490) 1505,440 ; 1465,1975 cw(c1490,1975) 1490,2000 ; 1470,7055 ccw(c1520,7055) 1520,7005 ; 1470,7265 cw(c1520,7265) 1520,7315 ; 1500,2000 cw(c1500,1975) 1525,1975 ; 1615,7315 cw(c1615,7265) 1665,7265 ccw(c1715,7265) 1715,7215 ; 1665,325 ccw(c1665,375) 1715,375 ; 1665,440 cw(c1665,390) 1715,390 ; 1754.29,2525 ccw(c1789.64,2560.36) 1825,2525 ; 1864.36,2561.64 ccw(c1829,2597) 1864.36,2632.36 ; 1990,4805 cw(c2040,4805) 2040,4855 ; 2060,374.17 ccw(c2110,374.17) 2110,324.17 ; 2060,389.17 cw(c2110,389.17) 2110,439.17 ; 2340,2320 ccw(c2340,2370) 2390,2370 ; 2340,2480 cw(c2340,2430) 2390,2430 ; 2835,1620 ccw(c2885,1620) 2885,1570 ; 2835,1975 cw(c2885,1975) 2885,2025 ; 2900,1570 ccw(c2900,1620) 2950,1620 ; 2915,7440 ccw(c2965,7440) 2965,7390 ; 2915,7875 cw(c2965,7875) 2965,7925 ; 2950,1675 cw(c3000,1675) 3000,1725 ; 2960,2165 ccw(c3010,2165) 3010,2115 ; 2980,7390 ccw(c2980,7440) 3030,7440 ; 3030,7530 cw(c3080,7530) 3080,7580 ; 3060,325 ccw(c3060,375) 3110,375 ; 3060,440 cw(c3060,390) 3110,390 ; 3085,7215 ccw(c3085,7265) 3135,7265 cw(c3185,7265) 3185,7315 ; 3125,2115 ccw(c3125,2165) 3175,2165 ; 3200,2595 ccw(c3200,2645) 3250,2645 ; 3215,7315 cw(c3215,7265) 3265,7265 ccw(c3315,7265) 3315,7215 ; 3360,7580 cw(c3360,7530) 3410,7530 ; 3410,7925 cw(c3410,7875) 3460,7875 ; 3620,1725 ccw(c3620,1775) 3670,1775 ; 3670,1795 cw(c3720,1795) 3720,1845 ; 3700,125 ccw(c3750,125) 3750,75 ; 3700,425 cw(c3750,425) 3750,475 ; 3800,1845 ccw(c3800,1895) 3850,1895 ; 3800,2025 cw(c3800,1975) 3850,1975 ; 3890,7215 ccw(c3890,7265) 3940,7265 ; 4060,7265 ccw(c4110,7265) 4110,7215 ; 4110,215 ccw(c4160,215) 4160,165 ; 4110,570 cw(c4160,570) 4160,620 ; 4158.3,620 ccw(c4115,645) 4165,645 ; 4165,1400 cw(c4215,1400) 4215,1450 ; 4345,1275 cw(c4395,1275) 4395,1325 ; 4360,165 ccw(c4360,215) 4410,215 ; 4360,650 cw(c4360,600) 4410,600 ; 4415,1325 ccw(c4415,1375) 4465,1375 ; 4415,1450 cw(c4415,1400) 4465,1400 ; 4590,7530 cw(c4640,7530) 4640,7580 ; 4685,7215 ccw(c4685,7265) 4735,7265 cw(c4785,7265) 4785,7315 ; 4815,7315 cw(c4815,7265) 4865,7265 ccw(c4915,7265) 4915,7215 ; 4895,5456 cw(c4895,5406) 4945,5406 ; 4920,7580 cw(c4920,7530) 4970,7530 ; 4970,7440 ccw(c5020,7440) 5020,7390 ; 4980,5965 cw(c4980,5915) 5030,5915 ; 5035,7390 ccw(c5035,7440) 5085,7440 ; 5035,7925 cw(c5035,7875) 5085,7875 ; 5105,6225 cw(c5105,6175) 5155,6175 ; 5160,290 cw(c5210,290) 5210,340 ; 5160,455 ccw(c5210,455) 5210,405 ; 5250,405 ccw(c5250,455) 5300,455 ; 5255,100 ccw(c5255,150) 5305,150 ; 5255,340 cw(c5255,290) 5305,290 ; 5620,505 ccw(c5670,505) 5670,455 ; 5680,5320 ccw(c5680,5350) 5710,5350 ; 5680,5390 cw(c5680,5360) 5710,5360 ; 5930,775 cw(c5980,775) 5980,825 ; 5975,825 ccw(c5975,875) 6025,875 ; 6005,4335 cw(c6055,4335) 6055,4385 ; 6025,1025 cw(c6075,1025) 6075,1075 ; 6090,5390 cw(c6090,5340) 6140,5340 ; 6110,5050 ccw(c6160,5050) 6160,5000 ; 6110,5110 cw(c6160,5110) 6160,5160 ; 6115,455 ccw(c6115,505) 6165,505 ; 6139.09,5350 ccw(c6169.09,5350) 6169.09,5320 ; 6160,5445 cw(c6160,5395) 6210,5395 ; 6165,530 cw(c6215,530) 6215,580 ; 6179.09,5320 ccw(c6179.09,5350) 6209.09,5350 ; 6285,7215 ccw(c6285,7265) 6335,7265 cw(c6385,7265) 6385,7315 ; 6385,4335 cw(c6435,4335) 6435,4385 ; 6450,580 ccw(c6450,630) 6500,630 ; 6500,810 cw(c6550,810) 6550,860 ; 6505,7005 ccw(c6505,7055) 6555,7055 ; 6505,7315 cw(c6505,7265) 6555,7265 ; 6645,860 ccw(c6645,910) 6695,910 ; 6755,4335 cw(c6805,4335) 6805,4385 ; 6840,5065 ccw(c6890,5065) 6890,5015 ; 6840,5145 cw(c6890,5145) 6890,5195 ; 6845,5445 cw(c6845,5395) 6895,5395 ; 6895,5350 ccw(c6925,5350) 6925,5320 ; 6915,5500 cw(c6915,5450) 6965,5450 ; 6935,5320 ccw(c6935,5350) 6965,5350 ; 7220,910 ccw(c7270,910) 7270,860 ; 7310,4495 cw(c7360,4495) 7360,4545 ; 7335,1075 cw(c7335,1025) 7385,1025 ; 7390,2420 ccw(c7440,2420) 7440,2370 ; 7415,860 cw(c7415,810) 7465,810 ; 7430,1250 cw(c7480,1250) 7480,1300 ; 7465,555 ccw(c7515,555) 7515,505 ; 7605,2370 ccw(c7605,2420) 7655,2420 ; 7775,3115 ccw(c7825,3115) 7825,3065 ; 7880,1300 cw(c7880,1250) 7930,1250 ; 7900,505 ccw(c7900,555) 7950,555 ; 7900,970 cw(c7900,920) 7950,920 ; 7900,1075 cw(c7900,1025) 7950,1025 ; 7900,5120 ccw(c7900,5170) 7950,5170 ; 7900,5320 cw(c7900,5270) 7950,5270 ; 7925,2815 ccw(c7925,2865) 7975,2865 ; 7925,3005 cw(c7925,2955) 7975,2955 ; 7925,3065 ccw(c7925,3115) 7975,3115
